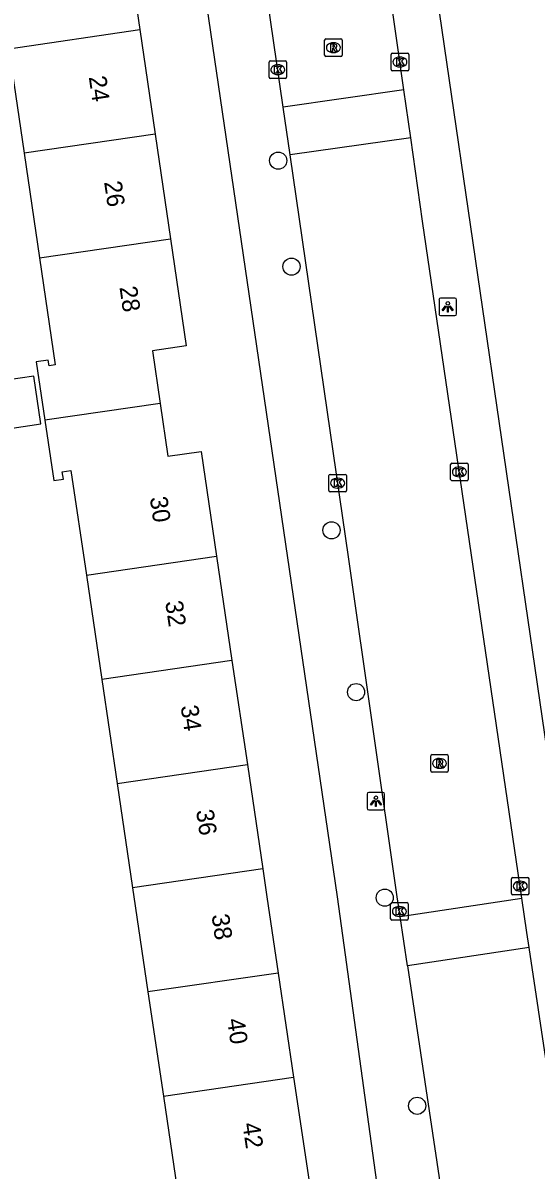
# Model space of a CAD drawing. Extents: x 159053 to 160041, y 380450 to 381422.
# Drawn here: x 159367.8 to 159397.1, y 380984.4 to 381049.8 of the extents above; entities that cross this region are included whole.
import ezdxf

# ---------------------------------------------------------------- set-up
doc = ezdxf.new("R2010")
doc.units = 0
for name, color, linetype in [('IMGEO_Boom', 7, 'Continuous'), ('IMGEO_Kolk', 7, 'Continuous'), ('IMGEO_Lichtpunt', 7, 'Continuous'), ('IMGEO_Pand', 7, 'Continuous'), ('IMGEO_Pand_nummerreeks', 7, 'Continuous'), ('IMGEO_Rijbaan_lokaal_open', 7, 'Continuous'), ('IMGEO_Rioolput', 7, 'Continuous'), ('IMGEO_Voetpad_open', 7, 'Continuous')]:
    doc.layers.add(name, color=color, linetype=linetype)

msp = doc.modelspace()

# ---------------------------------------------------------------- linework, layer by layer
at = {"layer": 'IMGEO_Boom'}
for centre in [(159382.372, 381041.927), (159383.129, 381035.889), (159385.41, 381020.873), (159386.808, 381011.654), (159388.442, 380999.945), (159390.289, 380988.092)]:
    msp.add_circle(centre, 0.489, dxfattribs=at)
at = {"layer": 'IMGEO_Kolk'}
for p, q in [((159381.847, 381046.684), (159381.847, 381047.536)), ((159381.922, 381047.61), (159382.774, 381047.61)), ((159382.848, 381047.536), (159382.848, 381046.684)), ((159388.807, 381047.121), (159388.807, 381047.973)), ((159388.882, 381048.047), (159389.734, 381048.047)), ((159389.295, 381047.827), (159389.32, 381047.827)), ((159389.808, 381047.973), (159389.808, 381047.121)), ((159382.358, 381046.83), (159382.333, 381046.83)), ((159382.335, 381047.39), (159382.36, 381047.39)), ((159389.734, 381047.047), (159388.882, 381047.047)), ((159389.318, 381047.267), (159389.293, 381047.267)), ((159382.774, 381046.61), (159381.922, 381046.61)), ((159392.196, 381023.771), (159392.196, 381024.623)), ((159392.271, 381024.697), (159393.123, 381024.697)), ((159393.197, 381024.623), (159393.197, 381023.771)), ((159385.259, 381023.132), (159385.259, 381023.984)), ((159385.334, 381024.058), (159386.186, 381024.058)), ((159386.26, 381023.984), (159386.26, 381023.132)), ((159392.707, 381023.917), (159392.682, 381023.917)), ((159392.684, 381024.477), (159392.709, 381024.477)), ((159385.77, 381023.278), (159385.745, 381023.278)), ((159385.747, 381023.838), (159385.772, 381023.838)), ((159393.123, 381023.697), (159392.271, 381023.697)), ((159386.186, 381023.058), (159385.334, 381023.058)), ((159395.736, 381001.101), (159396.588, 381001.101)), ((159395.661, 381000.175), (159395.661, 381001.027)), ((159396.149, 381000.881), (159396.174, 381000.881)), ((159396.662, 381001.027), (159396.662, 381000.175)), ((159396.588, 381000.101), (159395.736, 381000.101)), ((159396.172, 381000.321), (159396.147, 381000.321)), ((159388.776, 380998.735), (159388.776, 380999.587)), ((159388.851, 380999.661), (159389.703, 380999.661)), ((159389.264, 380999.441), (159389.289, 380999.441)), ((159389.777, 380999.587), (159389.777, 380998.735)), ((159389.703, 380998.661), (159388.851, 380998.661)), ((159389.287, 380998.881), (159389.262, 380998.881))]:
    msp.add_line(p, q, dxfattribs=at)
for points in [[(159381.847, 381046.684), (159381.847, 381047.536)], [(159381.922, 381047.61), (159382.774, 381047.61)], [(159382.848, 381047.536), (159382.848, 381046.684)], [(159388.807, 381047.121), (159388.807, 381047.973)], [(159388.882, 381048.047), (159389.734, 381048.047)], [(159389.128, 381047.747), (159389.251, 381047.747), (159389.251, 381047.596), (159389.381, 381047.747), (159389.545, 381047.747), (159389.399, 381047.596), (159389.552, 381047.347), (159389.4, 381047.347), (159389.315, 381047.511), (159389.251, 381047.444), (159389.251, 381047.347), (159389.128, 381047.347), (159389.128, 381047.747)], [(159389.808, 381047.973), (159389.808, 381047.121)], [(159382.168, 381047.31), (159382.291, 381047.31), (159382.291, 381047.159), (159382.421, 381047.31), (159382.585, 381047.31), (159382.439, 381047.159), (159382.592, 381046.91), (159382.44, 381046.91), (159382.355, 381047.074), (159382.291, 381047.007), (159382.291, 381046.91), (159382.168, 381046.91), (159382.168, 381047.31)], [(159389.734, 381047.047), (159388.882, 381047.047)], [(159382.774, 381046.61), (159381.922, 381046.61)], [(159392.196, 381023.771), (159392.196, 381024.623)], [(159392.271, 381024.697), (159393.123, 381024.697)], [(159393.197, 381024.623), (159393.197, 381023.771)], [(159385.259, 381023.132), (159385.259, 381023.984)], [(159385.334, 381024.058), (159386.186, 381024.058)], [(159386.26, 381023.984), (159386.26, 381023.132)], [(159392.517, 381024.397), (159392.64, 381024.397), (159392.64, 381024.246), (159392.77, 381024.397), (159392.934, 381024.397), (159392.788, 381024.246), (159392.941, 381023.997), (159392.789, 381023.997), (159392.704, 381024.161), (159392.64, 381024.094), (159392.64, 381023.997), (159392.517, 381023.997), (159392.517, 381024.397)], [(159385.58, 381023.758), (159385.703, 381023.758), (159385.703, 381023.607), (159385.833, 381023.758), (159385.997, 381023.758), (159385.851, 381023.607), (159386.004, 381023.358), (159385.852, 381023.358), (159385.767, 381023.522), (159385.703, 381023.455), (159385.703, 381023.358), (159385.58, 381023.358), (159385.58, 381023.758)], [(159393.123, 381023.697), (159392.271, 381023.697)], [(159386.186, 381023.058), (159385.334, 381023.058)], [(159395.736, 381001.101), (159396.588, 381001.101)], [(159395.661, 381000.175), (159395.661, 381001.027)], [(159395.982, 381000.801), (159396.105, 381000.801), (159396.105, 381000.65), (159396.235, 381000.801), (159396.399, 381000.801), (159396.253, 381000.65), (159396.406, 381000.401), (159396.254, 381000.401), (159396.169, 381000.565), (159396.105, 381000.498), (159396.105, 381000.401), (159395.982, 381000.401), (159395.982, 381000.801)], [(159396.662, 381001.027), (159396.662, 381000.175)], [(159396.588, 381000.101), (159395.736, 381000.101)], [(159388.776, 380998.735), (159388.776, 380999.587)], [(159388.851, 380999.661), (159389.703, 380999.661)], [(159389.097, 380999.361), (159389.22, 380999.361), (159389.22, 380999.21), (159389.35, 380999.361), (159389.514, 380999.361), (159389.368, 380999.21), (159389.521, 380998.961), (159389.369, 380998.961), (159389.284, 380999.125), (159389.22, 380999.058), (159389.22, 380998.961), (159389.097, 380998.961), (159389.097, 380999.361)], [(159389.777, 380999.587), (159389.777, 380998.735)], [(159389.703, 380998.661), (159388.851, 380998.661)]]:
    msp.add_lwpolyline(points, dxfattribs=at)
for centre, start, end in [((159381.924, 381047.534), 91.55205, 178.44795), ((159381.924, 381047.534), 91.55205, 178.44795), ((159382.772, 381047.534), 1.55205, 88.44795), ((159382.772, 381047.534), 1.55205, 88.44795), ((159388.884, 381047.971), 91.55205, 178.44795), ((159388.884, 381047.971), 91.55205, 178.44795), ((159389.732, 381047.971), 1.55205, 88.44795), ((159389.732, 381047.971), 1.55205, 88.44795), ((159388.884, 381047.123), 181.55205, 268.44795), ((159388.884, 381047.123), 181.55205, 268.44795), ((159389.732, 381047.123), 271.55205, 358.44795), ((159389.732, 381047.123), 271.55205, 358.44795), ((159381.924, 381046.686), 181.55205, 268.44795), ((159381.924, 381046.686), 181.55205, 268.44795), ((159382.772, 381046.686), 271.55205, 358.44795), ((159382.772, 381046.686), 271.55205, 358.44795), ((159392.273, 381024.621), 91.55205, 178.44795), ((159392.273, 381024.621), 91.55205, 178.44795), ((159393.121, 381024.621), 1.55205, 88.44795), ((159393.121, 381024.621), 1.55205, 88.44795), ((159385.336, 381023.982), 91.55205, 178.44795), ((159385.336, 381023.982), 91.55205, 178.44795), ((159386.184, 381023.982), 1.55205, 88.44795), ((159386.184, 381023.982), 1.55205, 88.44795), ((159392.273, 381023.773), 181.55205, 268.44795), ((159392.273, 381023.773), 181.55205, 268.44795), ((159393.121, 381023.773), 271.55205, 358.44795), ((159393.121, 381023.773), 271.55205, 358.44795), ((159385.336, 381023.134), 181.55205, 268.44795), ((159385.336, 381023.134), 181.55205, 268.44795), ((159386.184, 381023.134), 271.55205, 358.44795), ((159386.184, 381023.134), 271.55205, 358.44795), ((159395.738, 381001.025), 91.55205, 178.44795), ((159395.738, 381001.025), 91.55205, 178.44795), ((159396.586, 381001.025), 1.55205, 88.44795), ((159396.586, 381001.025), 1.55205, 88.44795), ((159395.738, 381000.177), 181.55205, 268.44795), ((159395.738, 381000.177), 181.55205, 268.44795), ((159396.586, 381000.177), 271.55205, 358.44795), ((159396.586, 381000.177), 271.55205, 358.44795), ((159388.853, 380999.585), 91.55205, 178.44795), ((159388.853, 380999.585), 91.55205, 178.44795), ((159389.701, 380999.585), 1.55205, 88.44795), ((159389.701, 380999.585), 1.55205, 88.44795), ((159388.853, 380998.737), 181.55205, 268.44795), ((159388.853, 380998.737), 181.55205, 268.44795), ((159389.701, 380998.737), 271.55205, 358.44795), ((159389.701, 380998.737), 271.55205, 358.44795)]:
    msp.add_arc(centre, 0.0765, start, end, dxfattribs=at)
for centre, major_axis, ratio, start_param, end_param in [((159389.294, 381047.547), (-0.387, 0.002), 0.722429, 4.712389, 7.853982), ((159389.319, 381047.547), (-0.39, 0.002), 0.717154, 1.570796, 4.712389), ((159382.334, 381047.11), (-0.387, 0.002), 0.722429, 4.712389, 7.853982), ((159382.359, 381047.11), (-0.39, 0.002), 0.717154, 1.570796, 4.712389), ((159392.683, 381024.197), (-0.387, 0.002), 0.722429, 4.712389, 7.853982), ((159392.708, 381024.197), (-0.39, 0.002), 0.717154, 1.570796, 4.712389), ((159385.746, 381023.558), (-0.387, 0.002), 0.722429, 4.712389, 7.853982), ((159385.771, 381023.558), (-0.39, 0.002), 0.717154, 1.570796, 4.712389), ((159396.148, 381000.601), (-0.387, 0.002), 0.722429, 4.712389, 7.853982), ((159396.173, 381000.601), (-0.39, 0.002), 0.717154, 1.570796, 4.712389), ((159389.263, 380999.161), (-0.387, 0.002), 0.722429, 4.712389, 7.853982), ((159389.288, 380999.161), (-0.39, 0.002), 0.717154, 1.570796, 4.712389)]:
    msp.add_ellipse(centre, major_axis=major_axis, ratio=ratio, start_param=start_param, end_param=end_param, dxfattribs=at)
at = {"layer": 'IMGEO_Lichtpunt'}
for p, q in [((159391.534, 381034.001), (159391.534, 381033.194)), ((159391.534, 381034.001), (159391.534, 381033.194)), ((159392.436, 381034.096), (159391.628, 381034.096)), ((159392.436, 381034.096), (159391.628, 381034.096)), ((159392.53, 381033.194), (159392.53, 381034.001)), ((159392.53, 381033.194), (159392.53, 381034.001)), ((159391.628, 381033.1), (159392.436, 381033.1)), ((159391.628, 381033.1), (159392.436, 381033.1)), ((159387.439, 381005.843), (159387.439, 381005.036)), ((159387.439, 381005.843), (159387.439, 381005.036)), ((159388.341, 381005.938), (159387.533, 381005.938)), ((159388.341, 381005.938), (159387.533, 381005.938)), ((159388.435, 381005.036), (159388.435, 381005.843)), ((159388.435, 381005.036), (159388.435, 381005.843)), ((159387.533, 381004.942), (159388.341, 381004.942)), ((159387.533, 381004.942), (159388.341, 381004.942))]:
    msp.add_line(p, q, dxfattribs=at)
for points in [[(159391.908, 381033.665), (159391.947, 381033.637), (159391.759, 381033.375), (159391.721, 381033.402), (159391.908, 381033.665)], [(159392.01, 381033.617), (159392.057, 381033.617), (159392.057, 381033.295), (159392.01, 381033.295), (159392.01, 381033.617)], [(159392.12, 381033.637), (159392.158, 381033.664), (159392.345, 381033.402), (159392.306, 381033.374), (159392.12, 381033.637)], [(159387.813, 381005.507), (159387.852, 381005.479), (159387.664, 381005.217), (159387.626, 381005.244), (159387.813, 381005.507)], [(159387.915, 381005.459), (159387.962, 381005.459), (159387.962, 381005.137), (159387.915, 381005.137), (159387.915, 381005.459)], [(159388.025, 381005.479), (159388.063, 381005.506), (159388.25, 381005.244), (159388.211, 381005.216), (159388.025, 381005.479)]]:
    msp.add_lwpolyline(points, dxfattribs=at)
for centre in [(159392.033, 381033.799), (159387.938, 381005.641)]:
    msp.add_circle(centre, 0.0994, dxfattribs=at)
for centre, start, end in [((159391.628, 381034.001), 90, 180), ((159391.628, 381034.001), 90, 180), ((159392.436, 381034.001), 0, 90), ((159392.436, 381034.001), 0, 90), ((159391.628, 381033.194), 180, 270), ((159391.628, 381033.194), 180, 270), ((159392.436, 381033.194), 270, 0), ((159392.436, 381033.194), 270, 360), ((159387.533, 381005.843), 90, 180), ((159387.533, 381005.843), 90, 180), ((159388.341, 381005.843), 0, 90), ((159388.341, 381005.843), 0, 90), ((159387.533, 381005.036), 180, 270), ((159387.533, 381005.036), 180, 270), ((159388.341, 381005.036), 270, 0), ((159388.341, 381005.036), 270, 360)]:
    msp.add_arc(centre, 0.0946, start, end, dxfattribs=at)
at = {"layer": 'IMGEO_Pand'}
for points in [[(159373.62, 381055.349), (159374.491, 381049.393)], [(159367.026, 381048.302), (159374.491, 381049.393)], [(159374.491, 381049.393), (159375.363, 381043.436)], [(159367.026, 381048.302), (159367.898, 381042.344)], [(159375.363, 381043.436), (159367.898, 381042.344)], [(159375.363, 381043.436), (159376.234, 381037.479)], [(159367.898, 381042.344), (159368.769, 381036.388)], [(159368.769, 381036.388), (159376.234, 381037.479)], [(159376.234, 381037.479), (159377.126, 381031.385), (159375.2, 381031.103), (159375.639, 381028.098)], [(159368.769, 381036.388), (159369.661, 381030.292), (159369.316, 381030.242), (159369.254, 381030.562), (159368.584, 381030.473), (159369.072, 381027.137)], [(159364.525, 381029.082), (159364.924, 381026.356), (159368.849, 381026.931), (159368.449, 381029.657), (159364.525, 381029.082)], [(159375.639, 381028.098), (159369.072, 381027.137)], [(159375.639, 381028.098), (159376.079, 381025.09), (159377.975, 381025.368), (159378.859, 381019.396)], [(159369.072, 381027.137), (159369.575, 381023.705), (159370.136, 381023.775), (159370.063, 381024.21), (159370.557, 381024.282), (159371.439, 381018.316)], [(159371.439, 381018.316), (159378.859, 381019.396)], [(159378.859, 381019.396), (159379.737, 381013.46)], [(159371.439, 381018.316), (159372.316, 381012.38)], [(159379.737, 381013.46), (159372.316, 381012.38)], [(159379.737, 381013.46), (159380.615, 381007.525)], [(159372.316, 381012.38), (159373.193, 381006.445)], [(159373.193, 381006.445), (159380.615, 381007.525)], [(159380.615, 381007.525), (159381.494, 381001.59)], [(159373.193, 381006.445), (159374.071, 381000.51)], [(159381.494, 381001.59), (159374.071, 381000.51)], [(159381.494, 381001.59), (159381.729, 381000), (159382.372, 380995.654)], [(159374.071, 381000.51), (159374.146, 381000), (159374.948, 380994.574)], [(159382.372, 380995.654), (159374.948, 380994.574)], [(159382.372, 380995.654), (159383.25, 380989.719)], [(159374.948, 380994.574), (159375.825, 380988.639)], [(159375.825, 380988.639), (159383.25, 380989.719)], [(159383.25, 380989.719), (159384.129, 380983.783)], [(159375.825, 380988.639), (159376.702, 380982.703)]]:
    msp.add_lwpolyline(points, dxfattribs=at)
at = {"layer": 'IMGEO_Rijbaan_lokaal_open'}
for points in [[(159389.532, 381045.961), (159385.799, 381072.168), (159383.303, 381088.805), (159382.253, 381096.095)], [(159382.658, 381044.981), (159380.323, 381061.093), (159375.359, 381095.076)], [(159389.532, 381045.961), (159382.658, 381044.981)], [(159389.922, 381043.228), (159389.532, 381045.961)], [(159383.053, 381042.25), (159382.658, 381044.981)], [(159389.922, 381043.228), (159383.053, 381042.25)], [(159396.262, 380999.919), (159390.597, 381038.488), (159389.922, 381043.228)], [(159389.315, 380998.881), (159389.147, 381000), (159386.389, 381019.228), (159383.053, 381042.25)], [(159389.315, 380998.881), (159396.262, 380999.919)], [(159396.672, 380997.098), (159396.542, 380997.966), (159396.262, 380999.919)], [(159389.737, 380996.062), (159389.315, 380998.881)], [(159396.672, 380997.098), (159389.737, 380996.062)], [(159399.423, 380978.652), (159398.743, 380983.277), (159396.672, 380997.098)], [(159389.737, 380996.062), (159392.402, 380978.279), (159392.726, 380976.187)]]:
    msp.add_lwpolyline(points, dxfattribs=at)
at = {"layer": 'IMGEO_Rioolput'}
for p, q in [((159385.015, 381047.94), (159385.015, 381048.792)), ((159385.09, 381048.866), (159385.942, 381048.866)), ((159386.016, 381048.792), (159386.016, 381047.94)), ((159385.503, 381048.646), (159385.528, 381048.646)), ((159385.942, 381047.866), (159385.09, 381047.866)), ((159385.526, 381048.086), (159385.501, 381048.086)), ((159391.06, 381007.167), (159391.06, 381008.019)), ((159391.135, 381008.093), (159391.987, 381008.093)), ((159391.548, 381007.873), (159391.573, 381007.873)), ((159392.061, 381008.019), (159392.061, 381007.167)), ((159391.987, 381007.093), (159391.135, 381007.093)), ((159391.571, 381007.313), (159391.546, 381007.313))]:
    msp.add_line(p, q, dxfattribs=at)
for points in [[(159385.015, 381047.94), (159385.015, 381048.792)], [(159385.09, 381048.866), (159385.942, 381048.866)], [(159386.016, 381048.792), (159386.016, 381047.94)], [(159385.604, 381048.564), (159385.352, 381048.566), (159385.352, 381048.166)], [(159385.352, 381048.166), (159385.476, 381048.166), (159385.476, 381048.328), (159385.487, 381048.328)], [(159385.53, 381048.485), (159385.476, 381048.485), (159385.476, 381048.404)], [(159385.476, 381048.404), (159385.528, 381048.404)], [(159385.534, 381048.299), (159385.605, 381048.166), (159385.745, 381048.166), (159385.68, 381048.292)], [(159385.942, 381047.866), (159385.09, 381047.866)], [(159391.06, 381007.167), (159391.06, 381008.019)], [(159391.135, 381008.093), (159391.987, 381008.093)], [(159391.649, 381007.791), (159391.397, 381007.793), (159391.397, 381007.393)], [(159391.575, 381007.712), (159391.521, 381007.712), (159391.521, 381007.631)], [(159391.521, 381007.631), (159391.573, 381007.631)], [(159392.061, 381008.019), (159392.061, 381007.167)], [(159391.987, 381007.093), (159391.135, 381007.093)], [(159391.397, 381007.393), (159391.521, 381007.393), (159391.521, 381007.555), (159391.532, 381007.555)], [(159391.579, 381007.526), (159391.65, 381007.393), (159391.79, 381007.393), (159391.725, 381007.519)]]:
    msp.add_lwpolyline(points, dxfattribs=at)
for centre, radius, start, end in [((159385.092, 381048.79), 0.0765, 91.55205, 178.44795), ((159385.092, 381048.79), 0.0765, 91.55205, 178.44795), ((159385.94, 381048.79), 0.0765, 1.55205, 88.44795), ((159385.94, 381048.79), 0.0765, 1.55205, 88.44795), ((159385.486, 381048.275), 0.0533, 26.02933, 88.69889), ((159385.512, 381048.593), 0.19, 274.7715, 282.96867), ((159385.536, 381048.389), 0.0964, 77.00612, 93.18647), ((159385.55, 381048.446), 0.0378, 276.66336, 79.67722), ((159385.603, 381048.454), 0.109, 350.36119, 89.41601), ((159385.601, 381048.454), 0.112, 277.58423, 350.98172), ((159385.585, 381048.239), 0.108, 29.51342, 73.79051), ((159385.092, 381047.942), 0.0765, 181.55205, 268.44795), ((159385.092, 381047.942), 0.0765, 181.55205, 268.44795), ((159385.94, 381047.942), 0.0765, 271.55205, 358.44795), ((159385.94, 381047.942), 0.0765, 271.55205, 358.44795), ((159391.137, 381008.017), 0.0765, 91.55205, 178.44795), ((159391.137, 381008.017), 0.0765, 91.55205, 178.44795), ((159391.557, 381007.82), 0.19, 274.7715, 282.96867), ((159391.581, 381007.616), 0.0964, 77.00612, 93.18647), ((159391.595, 381007.673), 0.0378, 276.66336, 79.67722), ((159391.648, 381007.681), 0.109, 350.36119, 89.41601), ((159391.646, 381007.681), 0.112, 277.58423, 350.98172), ((159391.985, 381008.017), 0.0765, 1.55205, 88.44795), ((159391.985, 381008.017), 0.0765, 1.55205, 88.44795), ((159391.137, 381007.169), 0.0765, 181.55205, 268.44795), ((159391.137, 381007.169), 0.0765, 181.55205, 268.44795), ((159391.531, 381007.502), 0.0533, 26.02933, 88.69889), ((159391.63, 381007.466), 0.108, 29.51342, 73.79051), ((159391.985, 381007.169), 0.0765, 271.55205, 358.44795), ((159391.985, 381007.169), 0.0765, 271.55205, 358.44795)]:
    msp.add_arc(centre, radius, start, end, dxfattribs=at)
for centre, major_axis, ratio, start_param, end_param in [((159385.502, 381048.366), (-0.387, 0.002), 0.722429, 4.712389, 7.853982), ((159385.527, 381048.366), (-0.39, 0.002), 0.717154, 1.570796, 4.712389), ((159391.547, 381007.593), (-0.387, 0.002), 0.722429, 4.712389, 7.853982), ((159391.572, 381007.593), (-0.39, 0.002), 0.717154, 1.570796, 4.712389)]:
    msp.add_ellipse(centre, major_axis=major_axis, ratio=ratio, start_param=start_param, end_param=end_param, dxfattribs=at)
at = {"layer": 'IMGEO_Voetpad_open'}
for points in [[(159388.726, 380978.358), (159385.752, 381000), (159373.296, 381085.027)], [(159386.52, 381084.815), (159398.888, 381000), (159401.289, 380983.538)]]:
    msp.add_lwpolyline(points, dxfattribs=at)

# ---------------------------------------------------------------- texts
at = {"layer": 'IMGEO_Pand_nummerreeks'}
for s, rotation, p in [('24', 278.32428, (159371.571, 381046.696)), ('26', 278.32428, (159372.447, 381040.709)), ('28', 278.32428, (159373.323, 381034.719)), ('30', 278.41748, (159375.05, 381022.731)), ('32', 278.41748, (159375.928, 381016.794)), ('34', 278.41748, (159376.808, 381010.849)), ('36', 278.41748, (159377.687, 381004.906)), ('38', 278.41665, (159378.569, 380998.952)), ('40', 278.41665, (159379.448, 380993.008)), ('42', 278.41665, (159380.327, 380987.069))]:
    msp.add_text(s, height=1, rotation=rotation, dxfattribs=at).set_placement(p)

doc.saveas('drawing.dxf')
